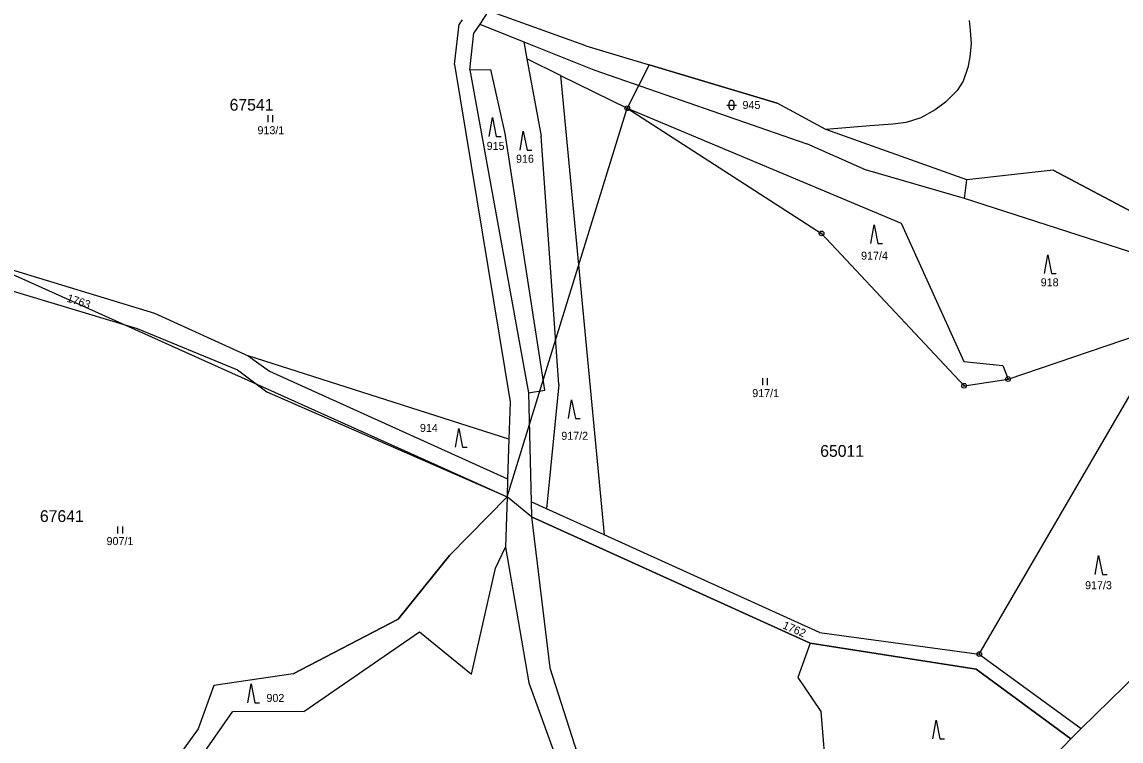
# Model space of a CAD drawing. Extents: x -546762 to -540209, y -1046851 to -1035694.
# Drawn here: x -543131.5 to -542898.1, y -1042369.7 to -1042217.1 of the extents above; entities that cross this region are included whole.
import ezdxf

# ---------------------------------------------------------------- set-up
doc = ezdxf.new("R2010")
doc.units = 0
for name, color, linetype in [('Vrstva 1', 7, 'Continuous'), ('Vrstva 18', 7, 'Continuous'), ('Vrstva 24', 7, 'Continuous'), ('Vrstva 25', 7, 'Continuous'), ('Vrstva 52', 7, 'Continuous'), ('Vrstva 53', 7, 'Continuous'), ('Vrstva 6', 7, 'Continuous')]:
    doc.layers.add(name, color=color, linetype=linetype)

msp = doc.modelspace()

# ---------------------------------------------------------------- linework, layer by layer
at = {"layer": 'Vrstva 1'}
for points in [[(-543032.39, -1042214.72), (-543034.27, -1042217.52)], [(-543011.73, -1042222.14), (-543032.39, -1042214.72)], [(-543039.65, -1042226.08), (-543038.63, -1042217.52)], [(-543038.01, -1042216.64), (-543038.63, -1042217.52)], [(-543034.27, -1042217.52), (-543035.51, -1042219.38)], [(-543034.27, -1042217.52), (-543024.93, -1042221.26)], [(-543036.36, -1042227.22), (-543035.51, -1042219.38)], [(-543024.93, -1042221.26), (-543010.06, -1042227.21)], [(-543011.73, -1042222.14), (-542971.12, -1042234.29)], [(-543017.17, -1042228.4), (-543024.26, -1042224.91)], [(-543024.26, -1042224.91), (-543021.24, -1042241.32)], [(-543039.65, -1042226.08), (-543027.83, -1042297.65)], [(-543036.36, -1042227.22), (-543023.92, -1042295.78)], [(-543010.06, -1042227.21), (-542964.8, -1042242.96)], [(-543017.17, -1042228.4), (-543002.98, -1042235.39)], [(-543017.17, -1042228.4), (-543007.88, -1042325.89)], [(-542960.8, -1042239.9), (-542971.12, -1042234.29)], [(-543002.98, -1042235.39), (-542944.81, -1042259.8)], [(-543002.98, -1042235.39), (-542961.69, -1042261.96)], [(-543017.49, -1042293.97), (-543021.24, -1042241.32)], [(-542930.87, -1042250.55), (-542960.8, -1042239.9)], [(-542952.38, -1042248.43), (-542964.8, -1042242.96)], [(-542931.35, -1042254.5), (-542952.38, -1042248.43)], [(-542912.5, -1042248.52), (-542930.87, -1042250.55)], [(-542912.5, -1042248.52), (-542889.56, -1042260.67)], [(-542931.35, -1042254.5), (-542930.87, -1042250.55)], [(-542944.81, -1042259.8), (-542931.48, -1042289.15)], [(-543173.16, -1042262.24), (-543106.99, -1042282.1)], [(-542961.69, -1042261.96), (-542931.44, -1042294.26)], [(-543146.18, -1042265.87), (-543103.35, -1042278.89)], [(-543103.35, -1042278.89), (-543083.45, -1042287.94)], [(-543106.99, -1042282.1), (-543085.69, -1042290.92)], [(-542922.09, -1042292.84), (-542894.38, -1042283.5)], [(-543083.45, -1042287.94), (-543078.95, -1042291.15)], [(-543028.09, -1042305.63), (-543083.45, -1042287.94)], [(-543085.69, -1042290.92), (-543079.48, -1042295.53)], [(-542931.48, -1042289.15), (-542923.2, -1042289.97)], [(-542923.2, -1042289.97), (-542922.09, -1042292.84)], [(-543078.95, -1042291.15), (-543028.36, -1042314.02)], [(-542931.44, -1042294.26), (-542922.09, -1042292.84)], [(-542928.22, -1042351.2), (-542894.2, -1042292.77)], [(-543079.48, -1042295.53), (-543028.48, -1042317.84)], [(-543017.49, -1042293.97), (-543020.1, -1042320.36)], [(-543027.83, -1042297.65), (-543028.09, -1042305.63)], [(-543023.92, -1042295.78), (-543023.38, -1042318.88)], [(-543028.09, -1042305.63), (-543028.36, -1042314.02)], [(-543028.36, -1042314.02), (-543028.48, -1042317.84)], [(-543040.73, -1042330.31), (-543028.48, -1042317.84)], [(-543028.48, -1042317.84), (-543028.82, -1042328.53)], [(-543020.1, -1042320.36), (-543023.38, -1042318.88)], [(-543023.38, -1042318.88), (-543023.31, -1042322.07)], [(-543007.88, -1042325.89), (-543020.1, -1042320.36)], [(-543023.31, -1042322.07), (-543019.4, -1042354.12)], [(-543023.31, -1042322.07), (-542964.14, -1042348.92)], [(-542962.14, -1042346.6), (-543007.88, -1042325.89)], [(-543051.61, -1042343.83), (-543040.73, -1042330.31)], [(-543028.82, -1042328.53), (-543023.83, -1042357.3)], [(-543073.88, -1042355.42), (-543051.61, -1042343.83)], [(-542906.61, -1042367.01), (-542882.26, -1042343.2)], [(-542962.14, -1042346.6), (-542928.22, -1042351.2)], [(-542964.14, -1042348.92), (-542928.9, -1042354.42)], [(-542928.22, -1042351.2), (-542906.61, -1042367.01)], [(-543073.88, -1042355.42), (-543090.71, -1042357.86)], [(-543019.4, -1042354.12), (-543004.19, -1042401.62)], [(-542928.9, -1042354.42), (-542908.81, -1042369.16)], [(-543090.71, -1042357.86), (-543094.07, -1042367.08)], [(-543023.83, -1042357.3), (-543006.68, -1042404.62)], [(-543094.07, -1042367.08), (-543099.86, -1042375.17)], [(-542908.81, -1042369.16), (-542906.61, -1042367.01)]]:
    msp.add_lwpolyline(points, dxfattribs=at)
at = {"layer": 'Vrstva 24'}
for centre, radius in [((-543002.98, -1042235.39), 0.5), ((-543002.98, -1042235.39), 0.1), ((-542961.69, -1042261.96), 0.5), ((-542961.69, -1042261.96), 0.1), ((-542922.09, -1042292.84), 0.5), ((-542922.09, -1042292.84), 0.1), ((-542931.44, -1042294.26), 0.5), ((-542931.44, -1042294.26), 0.1), ((-542928.22, -1042351.2), 0.5), ((-542928.22, -1042351.2), 0.1)]:
    msp.add_circle(centre, radius, dxfattribs=at)
at = {"layer": 'Vrstva 25'}
for p, q in [((-542981.8, -1042234.72), (-542979.8, -1042234.72)), ((-542981.3, -1042235.22), (-542981.3, -1042234.22)), ((-542980.3, -1042234.22), (-542980.3, -1042235.22)), ((-543079.21, -1042238.37), (-543079.21, -1042236.87)), ((-543078.21, -1042238.37), (-543078.21, -1042236.87)), ((-542974.16, -1042294.17), (-542974.16, -1042292.67)), ((-542973.16, -1042294.17), (-542973.16, -1042292.67)), ((-543111.1, -1042325.61), (-543111.1, -1042324.11)), ((-543110.1, -1042325.61), (-543110.1, -1042324.11))]:
    msp.add_line(p, q, dxfattribs=at)
for points in [[(-543032.27, -1042241.38), (-543031.57, -1042237.38), (-543030.77, -1042241.38), (-543029.77, -1042241.38)], [(-543025.73, -1042244.25), (-543025.03, -1042240.25), (-543024.23, -1042244.25), (-543023.23, -1042244.25)], [(-542951.27, -1042264.1), (-542950.57, -1042260.1), (-542949.77, -1042264.1), (-542948.77, -1042264.1)], [(-542914.37, -1042270.47), (-542913.67, -1042266.47), (-542912.87, -1042270.47), (-542911.87, -1042270.47)], [(-543015.47, -1042301.25), (-543014.77, -1042297.25), (-543013.97, -1042301.25), (-543012.97, -1042301.25)], [(-543039.43, -1042307.32), (-543038.73, -1042303.32), (-543037.93, -1042307.32), (-543036.93, -1042307.32)], [(-542903.59, -1042334.31), (-542902.89, -1042330.31), (-542902.09, -1042334.31), (-542901.09, -1042334.31)], [(-543083.54, -1042361.53), (-543082.84, -1042357.53), (-543082.04, -1042361.53), (-543081.04, -1042361.53)], [(-542938.08, -1042369.2), (-542937.38, -1042365.2), (-542936.58, -1042369.2), (-542935.58, -1042369.2)]]:
    msp.add_lwpolyline(points, dxfattribs=at)
for centre, start, end in [((-542980.8, -1042234.22), 0, 180), ((-542980.8, -1042235.22), 180, 0)]:
    msp.add_arc(centre, 0.5, start, end, dxfattribs=at)
at = {"layer": 'Vrstva 52'}
for points in [[(-542712.28, -1042173.01), (-542704.2, -1042187.61), (-542732.59, -1042233.37), (-542749.67, -1042229.86), (-542796.29, -1042213.78), (-542817.07, -1042206.61), (-542828.55, -1042210.13), (-542828.96, -1042212.41), (-542841.1, -1042230.89), (-542845.49, -1042238.03), (-542856.03, -1042247.12), (-542861.64, -1042253.87), (-542875.36, -1042260.19), (-542889.56, -1042260.67), (-542912.5, -1042248.52), (-542930.87, -1042250.55), (-542960.8, -1042239.9)], [(-542930.4, -1042216.76), (-542930.13, -1042218.9), (-542929.92, -1042221.67), (-542930.2, -1042224.51), (-542930.68, -1042226.73), (-542931.65, -1042229.63), (-542932.89, -1042231.64), (-542935.39, -1042234.07), (-542937.6, -1042235.73), (-542940.65, -1042237.39), (-542943.76, -1042238.43), (-542946.6, -1042238.77), (-542951.44, -1042239.12), (-542960.8, -1042239.9)], [(-542960.8, -1042239.9), (-542971.12, -1042234.29), (-542998.34, -1042226.15), (-543002.98, -1042235.39)], [(-543028.48, -1042317.84), (-543040.73, -1042330.31), (-543051.61, -1042343.83), (-543073.88, -1042355.42), (-543090.71, -1042357.86), (-543094.07, -1042367.08), (-543099.86, -1042375.17), (-543125.43, -1042401.77), (-543140.44, -1042404.67), (-543165.41, -1042363.31), (-543154.81, -1042335.03), (-543169.11, -1042293.13), (-543194.16, -1042279.71), (-543207.13, -1042243.97), (-543211.97, -1042235.36)], [(-543211.97, -1042235.36), (-543028.48, -1042317.84)], [(-543028.48, -1042317.84), (-543002.98, -1042235.39)], [(-543002.98, -1042235.39), (-542961.69, -1042261.96)], [(-542961.69, -1042261.96), (-542931.44, -1042294.26), (-542922.09, -1042292.84), (-542894.38, -1042283.5), (-542894.2, -1042292.77), (-542890.88, -1042322.29), (-542882.26, -1042343.2), (-542906.61, -1042367.01), (-542908.81, -1042369.16), (-542928.9, -1042354.42), (-542964.14, -1042348.92), (-543023.31, -1042322.07), (-543028.48, -1042317.84)]]:
    msp.add_lwpolyline(points, dxfattribs=at)
at = {"layer": 'Vrstva 6'}
for points in [[(-543024.93, -1042221.26), (-543024.26, -1042224.91)], [(-543036.36, -1042227.22), (-543031.9, -1042227.15)], [(-543028.9, -1042240.76), (-543031.9, -1042227.15)], [(-543020.48, -1042295.24), (-543028.9, -1042240.76)], [(-542876.7, -1042272.15), (-542931.35, -1042254.5)], [(-543023.92, -1042295.78), (-543020.48, -1042295.24)], [(-543030.94, -1042333), (-543028.82, -1042328.53)], [(-543036.05, -1042355.45), (-543030.94, -1042333)], [(-543071.64, -1042363.4), (-543047.07, -1042346.48)], [(-543047.07, -1042346.48), (-543036.05, -1042355.45)], [(-542964.14, -1042348.92), (-542966.76, -1042356.18)], [(-542966.76, -1042356.18), (-542961.86, -1042363.41)], [(-543128.55, -1042423.33), (-543086.77, -1042363.47)], [(-543071.64, -1042363.4), (-543086.77, -1042363.47)], [(-542961.86, -1042363.41), (-542960.64, -1042378.28)], [(-542908.81, -1042369.16), (-542936.06, -1042397.6)]]:
    msp.add_lwpolyline(points, dxfattribs=at)

# ---------------------------------------------------------------- texts
at = {"layer": 'Vrstva 18'}
for s, p in [('945', (-542978.49, -1042235.54)), ('913/1', (-543081.47, -1042240.89)), ('915', (-543032.81, -1042244.22)), ('916', (-543026.58, -1042246.95)), ('917/4', (-542953.31, -1042267.52)), ('918', (-542915.17, -1042273.17)), ('917/1', (-542976.42, -1042296.69)), ('914', (-543046.98, -1042304.07)), ('917/2', (-543016.96, -1042305.74)), ('907/1', (-543113.52, -1042328.08)), ('917/3', (-542905.75, -1042337.44)), ('902', (-543079.57, -1042361.37))]:
    msp.add_text(s, height=1.7, dxfattribs=at).set_placement(p)
for s, rotation, p in [('1763', 342.2571, (-543122.08, -1042276.39)), ('1762', 336.5412, (-542970.13, -1042345.69))]:
    msp.add_text(s, height=1.7, rotation=rotation, dxfattribs=at).set_placement(p)
at = {"layer": 'Vrstva 53'}
for s, p in [('67541', (-543087.39, -1042235.9)), ('65011', (-542961.99, -1042309.35)), ('67641', (-543127.67, -1042323.18))]:
    msp.add_text(s, height=2.5, dxfattribs=at).set_placement(p)

doc.saveas('drawing.dxf')
